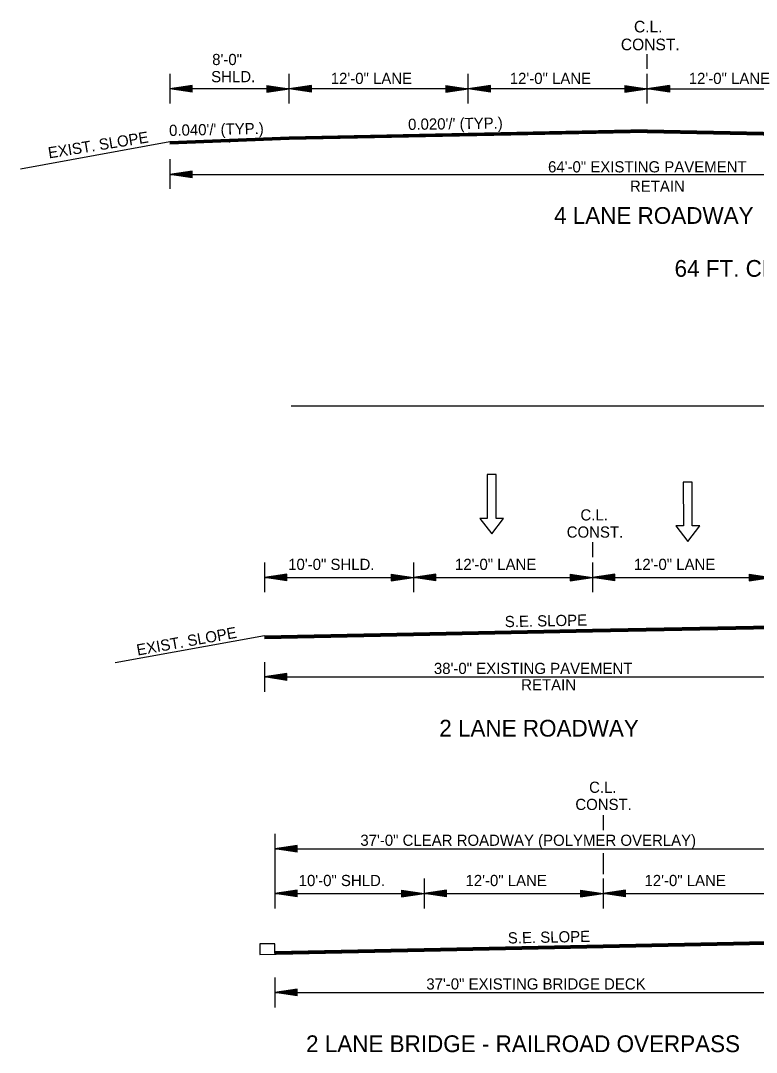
# Model space of a CAD drawing. Extents: x 545241 to 1930787, y -1971772 to 596640.
# Drawn here: x 546706 to 547199, y -1949540 to -1948848 of the extents above; entities that cross this region are included whole.
import ezdxf

# ---------------------------------------------------------------- set-up
doc = ezdxf.new("R2010")
doc.units = 0
doc.layers.add('R_Border', color=7, linetype='Continuous')
doc.layers.add('R_Draft', color=7, linetype='Continuous')

# ---------------------------------------------------------------- blocks, each defined once
blk = doc.blocks.new('ARROW')
at = {"layer": 'R_Draft'}
for p, q in [((-2, 0.3), (0, 0)), ((-2, 0.3), (-2, -0.3)), ((-2, 0.25), (-0.334, 0)), ((-2, 0.199), (-0.678, 0)), ((-2, 0.149), (-1.011, 0)), ((-2, 0.097), (-1.35, 0)), ((-2, 0.047), (-1.684, 0)), ((-2, -0.3), (0, 0)), ((-2, -0.098), (-1.35, 0)), ((-2, -0.199), (-0.678, 0)), ((-2, -0.25), (-0.334, 0)), ((-2, -0.149), (-1.011, 0)), ((-2, -0.047), (-1.684, 0))]:
    blk.add_line(p, q, dxfattribs=at)

msp = doc.modelspace()

# ---------------------------------------------------------------- linework, layer by layer
at = {"layer": 'R_Border'}
for p, q in [((546887.2, -1949106.18), (547733.92, -1949106.18)), ((547089.31, -1949197.63), (547089.31, -1949207.63)), ((546869.31, -1949211.23), (546869.31, -1949231.23)), ((546969.31, -1949211.23), (546969.31, -1949231.23)), ((547089.31, -1949211.23), (547089.31, -1949231.23)), ((546869.31, -1949221.23), (547249.31, -1949221.23)), ((546869.31, -1949260.43), (546769.31, -1949278.43)), ((546869.31, -1949278.03), (546869.31, -1949298.03)), ((546869.31, -1949288.03), (547249.31, -1949288.03)), ((547096.35, -1949380.81), (547096.35, -1949390.81)), ((546876.35, -1949393.31), (546876.35, -1949443.31)), ((546876.35, -1949403.31), (547246.35, -1949403.31)), ((547096.35, -1949406.31), (547096.35, -1949420.31)), ((546976.35, -1949423.31), (546976.35, -1949443.31)), ((547096.35, -1949423.31), (547096.35, -1949443.31)), ((546876.35, -1949433.31), (547246.35, -1949433.31)), ((546876.35, -1949489.71), (546876.35, -1949509.71)), ((546876.35, -1949499.71), (547246.35, -1949499.71))]:
    msp.add_line(p, q, dxfattribs=at)
for points in [[(547126.01, -1948880.15), (547126.01, -1948870.15)], [(546869.31, -1949260.43), (546969.31, -1949258.43), (547089.31, -1949256.03), (547209.31, -1949253.63), (547259.31, -1949252.63)], [(546869.31, -1949260.73), (546969.31, -1949258.73), (547089.31, -1949256.33), (547209.31, -1949253.93), (547259.31, -1949252.93)], [(546869.31, -1949261.03), (546969.31, -1949259.03), (547089.31, -1949256.63), (547209.31, -1949254.23), (547259.31, -1949253.23)], [(546869.31, -1949261.33), (546969.31, -1949259.33), (547089.31, -1949256.93), (547209.31, -1949254.53), (547259.31, -1949253.53)], [(546869.31, -1949261.63), (546969.31, -1949259.63), (547089.31, -1949257.23), (547209.31, -1949254.83), (547259.31, -1949253.83)], [(546869.31, -1949261.93), (546969.31, -1949259.93), (547089.31, -1949257.53), (547209.31, -1949255.13), (547259.31, -1949254.13)], [(546869.31, -1949262.23), (546969.31, -1949260.23), (547089.31, -1949257.83), (547209.31, -1949255.43), (547259.31, -1949254.43)], [(546866.35, -1949474.11), (546976.35, -1949471.91), (547096.35, -1949469.51), (547216.35, -1949467.11), (547266.35, -1949466.11)], [(546876.35, -1949473.61), (546876.35, -1949467.11), (546866.35, -1949467.11), (546866.35, -1949474.11)], [(546876.35, -1949472.11), (546976.35, -1949470.11), (547096.35, -1949467.71), (547216.35, -1949465.31), (547266.35, -1949464.31)], [(546876.35, -1949472.41), (546976.35, -1949470.41), (547096.35, -1949468.01), (547216.35, -1949465.61), (547266.35, -1949464.61)], [(546876.35, -1949472.71), (546976.35, -1949470.71), (547096.35, -1949468.31), (547216.35, -1949465.91), (547266.35, -1949464.91)], [(546876.35, -1949473.01), (546976.35, -1949471.01), (547096.35, -1949468.61), (547216.35, -1949466.21), (547266.35, -1949465.21)], [(546876.35, -1949473.31), (546976.35, -1949471.31), (547096.35, -1949468.91), (547216.35, -1949466.51), (547266.35, -1949465.51)], [(546876.35, -1949473.61), (546976.35, -1949471.61), (547096.35, -1949469.21), (547216.35, -1949466.81), (547266.35, -1949465.81)]]:
    msp.add_lwpolyline(points, dxfattribs=at)
for points in [[(547013.72, -1949181.67), (547021.73, -1949192.05), (547029.72, -1949181.66), (547024.72, -1949181.66), (547024.69, -1949152.24), (547018.69, -1949152.24), (547018.72, -1949181.67)], [(547145.22, -1949186.67), (547153.23, -1949197.05), (547161.22, -1949186.66), (547156.22, -1949186.66), (547156.18, -1949157.24), (547150.18, -1949157.24), (547150.22, -1949186.67)]]:
    msp.add_lwpolyline(points, close=True, dxfattribs=at)
at = {"layer": 'R_Draft'}
for p, q in [((547126.01, -1948880.15), (547126.01, -1948870.15)), ((546806.01, -1948883.38), (546806.01, -1948903.38)), ((546886.01, -1948903.38), (546886.01, -1948883.49)), ((547006.01, -1948903.38), (547006.01, -1948883.49)), ((547126.01, -1948903.38), (547126.01, -1948883.49)), ((547126.01, -1948903.38), (547126.01, -1948883.49)), ((546821.01, -1948891.13), (546806.01, -1948893.38)), ((546886.01, -1948893.38), (546806.01, -1948893.38)), ((546821.01, -1948895.63), (546806.01, -1948893.38)), ((546821.01, -1948891.51), (546808.52, -1948893.38)), ((546821.01, -1948895.26), (546808.52, -1948893.38)), ((546821.01, -1948891.89), (546811.1, -1948893.38)), ((546821.01, -1948894.87), (546811.1, -1948893.38)), ((546821.01, -1948892.26), (546813.59, -1948893.38)), ((546821.01, -1948894.5), (546813.59, -1948893.38)), ((546821.01, -1948892.65), (546816.14, -1948893.38)), ((546821.01, -1948894.11), (546816.14, -1948893.38)), ((546821.01, -1948893.03), (546818.64, -1948893.38)), ((546821.01, -1948893.73), (546818.64, -1948893.38)), ((546821.01, -1948895.63), (546821.01, -1948891.13)), ((546871.01, -1948891.13), (546886.01, -1948893.38)), ((546871.01, -1948891.13), (546871.01, -1948895.63)), ((546871.01, -1948891.51), (546883.51, -1948893.38)), ((546871.01, -1948891.89), (546880.93, -1948893.38)), ((546871.01, -1948892.26), (546878.43, -1948893.38)), ((546871.01, -1948892.65), (546875.89, -1948893.38)), ((546871.01, -1948893.03), (546873.38, -1948893.38)), ((546871.01, -1948895.63), (546886.01, -1948893.38)), ((546871.01, -1948894.12), (546875.89, -1948893.38)), ((546871.01, -1948894.87), (546880.93, -1948893.38)), ((546871.01, -1948895.26), (546883.51, -1948893.38)), ((546871.01, -1948894.5), (546878.43, -1948893.38)), ((546871.01, -1948893.73), (546873.38, -1948893.38)), ((546901.01, -1948891.13), (546886.01, -1948893.38)), ((547006.01, -1948893.38), (546886.01, -1948893.38)), ((546901.01, -1948895.63), (546886.01, -1948893.38)), ((546901.01, -1948891.51), (546888.52, -1948893.38)), ((546901.01, -1948895.26), (546888.52, -1948893.38)), ((546901.01, -1948891.89), (546891.1, -1948893.38)), ((546901.01, -1948894.87), (546891.1, -1948893.38)), ((546901.01, -1948892.26), (546893.59, -1948893.38)), ((546901.01, -1948894.5), (546893.59, -1948893.38)), ((546901.01, -1948892.65), (546896.14, -1948893.38)), ((546901.01, -1948894.11), (546896.14, -1948893.38)), ((546901.01, -1948893.03), (546898.64, -1948893.38)), ((546901.01, -1948893.73), (546898.64, -1948893.38)), ((546901.01, -1948895.63), (546901.01, -1948891.13)), ((546991.01, -1948891.13), (547006.01, -1948893.38)), ((546991.01, -1948891.13), (546991.01, -1948895.63)), ((546991.01, -1948891.51), (547003.51, -1948893.38)), ((546991.01, -1948891.89), (547000.93, -1948893.38)), ((546991.01, -1948892.26), (546998.43, -1948893.38)), ((546991.01, -1948892.65), (546995.89, -1948893.38)), ((546991.01, -1948893.03), (546993.38, -1948893.38)), ((546991.01, -1948895.63), (547006.01, -1948893.38)), ((546991.01, -1948894.12), (546995.89, -1948893.38)), ((546991.01, -1948894.87), (547000.93, -1948893.38)), ((546991.01, -1948895.26), (547003.51, -1948893.38)), ((546991.01, -1948894.5), (546998.43, -1948893.38)), ((546991.01, -1948893.73), (546993.38, -1948893.38)), ((547021.01, -1948891.13), (547006.01, -1948893.38)), ((547126.01, -1948893.38), (547006.01, -1948893.38)), ((547021.01, -1948895.63), (547006.01, -1948893.38)), ((547021.01, -1948891.51), (547008.52, -1948893.38)), ((547021.01, -1948895.26), (547008.52, -1948893.38)), ((547021.01, -1948891.89), (547011.1, -1948893.38)), ((547021.01, -1948894.87), (547011.1, -1948893.38)), ((547021.01, -1948892.26), (547013.59, -1948893.38)), ((547021.01, -1948894.5), (547013.59, -1948893.38)), ((547021.01, -1948892.65), (547016.14, -1948893.38)), ((547021.01, -1948894.11), (547016.14, -1948893.38)), ((547021.01, -1948893.03), (547018.64, -1948893.38)), ((547021.01, -1948893.73), (547018.64, -1948893.38)), ((547021.01, -1948895.63), (547021.01, -1948891.13)), ((547111.01, -1948891.13), (547126.01, -1948893.38)), ((547111.01, -1948891.13), (547111.01, -1948895.63)), ((547111.01, -1948891.51), (547123.51, -1948893.38)), ((547111.01, -1948891.89), (547120.93, -1948893.38)), ((547111.01, -1948892.26), (547118.43, -1948893.38)), ((547111.01, -1948892.65), (547115.89, -1948893.38)), ((547111.01, -1948893.03), (547113.38, -1948893.38)), ((547111.01, -1948895.63), (547126.01, -1948893.38)), ((547111.01, -1948894.12), (547115.89, -1948893.38)), ((547111.01, -1948894.87), (547120.93, -1948893.38)), ((547111.01, -1948895.26), (547123.51, -1948893.38)), ((547111.01, -1948894.5), (547118.43, -1948893.38)), ((547111.01, -1948893.73), (547113.38, -1948893.38)), ((547141.01, -1948891.13), (547126.01, -1948893.38)), ((547126.01, -1948893.38), (547246.01, -1948893.38)), ((547141.01, -1948895.63), (547126.01, -1948893.38)), ((547141.01, -1948891.51), (547128.52, -1948893.38)), ((547141.01, -1948895.26), (547128.52, -1948893.38)), ((547141.01, -1948891.89), (547131.1, -1948893.38)), ((547141.01, -1948894.87), (547131.1, -1948893.38)), ((547141.01, -1948892.26), (547133.59, -1948893.38)), ((547141.01, -1948894.5), (547133.59, -1948893.38)), ((547141.01, -1948892.65), (547136.14, -1948893.38)), ((547141.01, -1948894.12), (547136.14, -1948893.38)), ((547141.01, -1948893.03), (547138.64, -1948893.38)), ((547141.01, -1948893.73), (547138.64, -1948893.38)), ((547141.01, -1948891.13), (547141.01, -1948895.63)), ((547126.01, -1948920.99), (546886.01, -1948925.79)), ((547126.02, -1948921.29), (546886.01, -1948926.09)), ((547126.02, -1948921.59), (546886.01, -1948926.39)), ((547126.03, -1948921.89), (546886.01, -1948926.69)), ((547126.03, -1948922.19), (546886.01, -1948926.99)), ((547126.04, -1948922.49), (546886.01, -1948927.29)), ((547126.04, -1948922.66), (546886.01, -1948927.46)), ((547125.98, -1948922.49), (547366.01, -1948927.29)), ((547125.98, -1948922.66), (547366.01, -1948927.46)), ((547125.99, -1948921.89), (547366.01, -1948926.69)), ((547125.99, -1948922.19), (547366.01, -1948926.99)), ((547126, -1948921.29), (547366.01, -1948926.09)), ((547126, -1948921.59), (547366.01, -1948926.39)), ((547126.01, -1948920.99), (547366.01, -1948925.79)), ((546806.01, -1948928.99), (546705.94, -1948947.36)), ((546886.01, -1948925.79), (546806.01, -1948928.99)), ((546886.01, -1948926.09), (546806.01, -1948929.29)), ((546886.01, -1948926.39), (546806.01, -1948929.59)), ((546886.01, -1948926.69), (546806.01, -1948929.89)), ((546886.01, -1948926.99), (546806.01, -1948930.19)), ((546886.01, -1948927.29), (546806.01, -1948930.49)), ((546886.01, -1948927.46), (546806.01, -1948930.66)), ((546846.01, -1948927.79), (546846.01, -1948929.46)), ((546806.01, -1948940.6), (546806.01, -1948960.6)), ((546821.01, -1948948.6), (546806.01, -1948950.85)), ((546806.01, -1948950.85), (547446.01, -1948950.93)), ((546821.01, -1948953.1), (546806.01, -1948950.85)), ((546821.01, -1948948.97), (546808.52, -1948950.85)), ((546821.01, -1948952.72), (546808.52, -1948950.85)), ((546821.01, -1948949.35), (546811.1, -1948950.85)), ((546821.01, -1948952.34), (546811.1, -1948950.85)), ((546821.01, -1948949.73), (546813.59, -1948950.85)), ((546821.01, -1948951.96), (546813.59, -1948950.85)), ((546821.01, -1948950.11), (546816.14, -1948950.85)), ((546821.01, -1948951.57), (546816.14, -1948950.85)), ((546821.01, -1948950.49), (546818.64, -1948950.85)), ((546821.01, -1948951.2), (546818.64, -1948950.85)), ((546821.01, -1948953.1), (546821.01, -1948948.6))]:
    msp.add_line(p, q, dxfattribs=at)

# ---------------------------------------------------------------- block references
at = {"layer": 'R_Border', "xscale": 7.5, "yscale": 7.5, "rotation": 180}
for p in [(546869.31, -1949221.23), (546969.31, -1949221.23), (547089.31, -1949221.23), (546869.31, -1949288.03), (546876.35, -1949403.31), (546876.35, -1949433.31), (546976.35, -1949433.31), (547096.35, -1949433.31), (546876.35, -1949499.71)]:
    msp.add_blockref('ARROW', p, dxfattribs=at)
at = {"layer": 'R_Border', "xscale": 7.5, "yscale": 7.5}
for p in [(546969.31, -1949221.23), (547089.31, -1949221.23), (547209.31, -1949221.23), (546976.35, -1949433.31), (547096.35, -1949433.31)]:
    msp.add_blockref('ARROW', p, dxfattribs=at)

# ---------------------------------------------------------------- texts
at = {"layer": 'R_Border'}
for s, height, p in [('C.L.', 7.5, (547081.22, -1949183.05)), ('CONST.', 7.5, (547072.01, -1949194.55)), ('10\'-0" SHLD.', 7.5, (546885.3, -1949216.23)), ('12\'-0" LANE', 7.5, (546997.13, -1949216.23)), ('12\'-0" LANE', 7.5, (547117.13, -1949216.23)), ('38\'-0" EXISTING PAVEMENT', 7.5, (546982.99, -1949286.03)), ('RETAIN', 7.5, (547041.51, -1949297.03)), ('2 LANE ROADWAY', 11.25, (546986.59, -1949328.03)), ('C.L.', 7.5, (547087.02, -1949365.76)), ('CONST.', 7.5, (547077.8, -1949377.26)), ('37\'-0" CLEAR ROADWAY (POLYMER OVERLAY)', 7.5, (546933.67, -1949401.31)), ('10\'-0" SHLD.', 7.5, (546892.33, -1949428.31)), ('12\'-0" LANE', 7.5, (547004.16, -1949428.31)), ('12\'-0" LANE', 7.5, (547124.16, -1949428.31)), ('37\'-0" EXISTING BRIDGE DECK', 7.5, (546977.9, -1949497.71)), ('2 LANE BRIDGE - RAILROAD OVERPASS', 11.25, (546897.29, -1949539.71))]:
    msp.add_text(s, height=height, dxfattribs=at).set_placement(p)
for s, rotation, p in [('S.E. SLOPE', 1.1458, (547030.58, -1949254.63)), ('EXIST. SLOPE', 10.204, (546784.38, -1949273.72)), ('S.E. SLOPE', 1.1458, (547032.61, -1949466.85))]:
    msp.add_text(s, height=7.5, rotation=rotation, dxfattribs=at).set_placement(p)
at = {"layer": 'R_Draft'}
for s, height, p in [('C.L.', 7.8, (547117.12, -1948855.62)), ('CONST.', 7.8, (547108.33, -1948867.58)), ('8\'-0" ', 7.5, (546834.35, -1948877.52)), ('SHLD.', 7.5, (546833.67, -1948889.02)), ('12\'-0" LANE', 7.5, (546913.83, -1948890.21)), ('12\'-0" LANE', 7.5, (547033.83, -1948890.21)), ('12\'-0" LANE', 7.5, (547153.83, -1948890.21)), ('64\'-0" EXISTING PAVEMENT', 7.5, (547059.5, -1948949.52)), ('RETAIN', 7.5, (547114.41, -1948962.53)), ('4 LANE ROADWAY', 11.25, (547063.53, -1948984.04)), ('64 FT. CLEAR ROADWAY BRIDGE - POLYMER OVERLAY', 11.25, (547144.31, -1949019.56))]:
    msp.add_text(s, height=height, dxfattribs=at).set_placement(p)
for s, rotation, p in [("0.040'/' (TYP.)", 1.31838, (546805.54, -1948925.11)), ("0.020'/' (TYP.)", 0.87191, (546965.74, -1948921.05)), ('EXIST. SLOPE', 9.15344, (546724.96, -1948940.19))]:
    msp.add_text(s, height=7.5, rotation=rotation, dxfattribs=at).set_placement(p)

doc.saveas('drawing.dxf')
